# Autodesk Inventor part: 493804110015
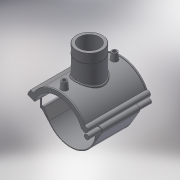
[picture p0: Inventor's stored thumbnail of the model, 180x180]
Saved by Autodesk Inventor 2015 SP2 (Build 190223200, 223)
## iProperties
Created: 2017-07
Part Number: 493804110015
Material: Generic
Description: PLASSON TRANSITION SADDLE 110-1.1/2"
Document SubType Name: Modeling
Designer: KIM
Density: 1 g/cm^3
Appearance: Default
Author: KIM
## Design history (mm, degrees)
derived "493804.ipt"
feature "Solid1::493804.ipt"
tag "TaggingFeature1"
body "Solid1"
other parameters: "d1" = 129.8, "d2" = 142, "d3" = 27.5, "d4" = 118, "d5" = 0, "d6" = 0.1, "d8" = 0, "d19" = 6, "d20" = 6, "d21" = 70.8, "d23" = 0, "d24" = 35.4, "d26" = 0, "d27" = 3, "d28" = 3, "d29" = 3, "d30" = 36.66667, "d31" = 6, "d32" = 0, "d33" = 0, "d34" = 0.6, "d40" = 67.496, "d41" = 62.783, "d43" = 0, "d45" = 0, "d47" = 117.9, "d48" = 58.2985, "d50" = 0, "d70" = 15, "d72" = 0, "d73" = 6, "d75" = 5, "d76" = 0, "d77" = 5.5, "d78" = 85, "d79" = 15, "d80" = 47.2, "d82" = 5 deg, "d84" = 4, "d85" = 14, "d86" = 0, "d87" = 3, "d88" = 0, "d89" = 1, "d90" = 1, "d91" = 94.4, "d92" = 0, "d93" = 0.5, "d94" = 57.89474, "d96" = 132.396, "d97" = 2.36, "d98" = 0, "d102" = 1.34535, "d103" = 44.845, "d104" = 31.8, "d105" = 0, "d106" = 35.876, "d108" = 0, "d109" = -17.66667, "d111" = 0.5, "d112" = 0.5, "d113" = 0, "d114" = 0.5, "d117" = 0.44845, "d120" = 140 deg, "d121" = 24.228, "d122" = 20 deg, "d123" = 259.6, "d124" = 77.88, "d126" = 0, "d143" = 113.3, "d145" = 15.23077, "d149" = 1.65, "d150" = 16.75385, "d153" = 118, "d154" = 0, "d156" = 64.9, "d157" = 160 deg, "d159" = 3.96, "d161" = 1.65, "d162" = 70.8, "d163" = 0, "d164" = 55, "d167" = 11, "d168" = 63.31707, "d170" = 2.1, "d172" = 0, "d173" = 1, "d175" = 55, "d176" = 20 deg, "d177" = 7.7, "d178" = 19.8, "d180" = 0, "d183" = 7.92, "d184" = 6.16, "d185" = 38.35, "d186" = 38.35, "d187" = 64.9, "d188" = 5.94, "d189" = 7.7, "d190" = 0, "d191" = 77.88, "d193" = 4.2, "d194" = 2.95, "d195" = 90 deg, "d197" = 0, "d199" = 0, "B_" = 142, "H_" = 53, "L_" = 118, "d_t" = 6, "G_" = 44.845, "d148" = 1.65, "d160" = 1.65, "d169" = 2.1, "d192" = 4.2
